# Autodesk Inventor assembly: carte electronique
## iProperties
Author: Administrateur
Created: 2001-04
Part Number: carte electronique
Document SubType Name: Assemblage
Designer: Administrateur
Control State: 0
Master: False
Checked Out: False
PropertySet Name: Design Tracking Control
Shininess: 60.0
PropertySet Name: _Private Model Information
Length Units: 11269
Angle Units: 11283
Time Units: 11279
Mass Units: 11290
Length Display Precision: 3
Angle Display Precision: 2
Compacted: False
Density: 0.0
Volumn: 0.0
Area: 0.0
PropertySet Name: Model Information
